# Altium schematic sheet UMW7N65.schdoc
size 127 x 101 mm
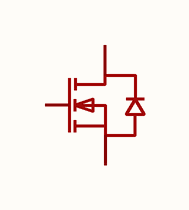
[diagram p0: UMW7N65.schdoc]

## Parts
Q?  7n65f_c347321  [TO-220F-3_L10.2-W4.7-P2.54-L]  (value not drawn)

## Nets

Not connected (* = marked no-connect by the designer): Q? 1(G) 2(D) 3(S)

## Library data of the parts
Q? = 7n65f_c347321: 数量:1个N沟道;漏源电压(Vdss):650V;连续漏极电流(Id):7A;导通电阻(RDS(on)):1.1Ω@10V;耗散功率(Pd):83W;阈值电压(Vgs(th)):4V@250uA;; Manufacturer: UMW(友台半导体); ManufacturerPart: 7N65F; Symbol: UMW7N65; AddInBom: yes; ModelId: b5990cdf67854b65a85fdb5429325fb8; ModelTransform: 399.999,185.039,0,0,0,0,0,10.354,-118.11; Number: 1个N沟道; Drain to Source Voltage: 650V; Current - Continuous Drain(Id): 7A; Pd - Power Dissipation: 83W; Gate Charge(Qg): 28nC@10V; Input Capacitance(Ciss): 955pF; Reverse Transfer Capacitance (Crss@Vds): 11.3pF; Type: N沟道; Output Capacitance(Coss): 120pF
